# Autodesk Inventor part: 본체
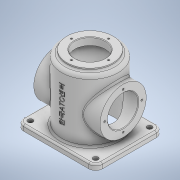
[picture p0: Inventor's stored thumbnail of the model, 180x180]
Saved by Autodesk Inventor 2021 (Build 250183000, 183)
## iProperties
Created: 2021-02
Part Number: 본체
Material: 알루미늄 6061
Document SubType Name: Modeling
Designer: 201-05
Density: 2.7 g/cm^3
Appearance: 기본값
Mass: 1235.48 g
Surface Area: 1067.61 cm^2
Volume: 457.584 cm^3
Author: 201-05
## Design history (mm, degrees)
sketch "스케치1"
  geometry: L1 (70, -60)-(-70, -60); L2 (-70, -60)-(-70, 60); L3 (-70, 60)-(70, 60); L4 (70, 60)-(70, -60); L5 (70, -60)-(-70, 60); L6 (-70, -60)-(70, 60); 1 further point
  constraints: 12 end point, 2 midpoint, 2 parallel, 1 horizontal, 1 perpendicular
  dimensions: "d0" = 140 distance of L2.end L3.end; "d1" = 120 distance of L1.end L2.end
extrude "돌출1" new body sketch "스케치1" distance "d2" = 10; taper "d3" = 0 deg
fillet "모깎기1" dims "d4" = 12
fillet "모깎기2" dims "d5" = 3
sketch "스케치2"
  geometry: A1 r 12 centre (-58, -48) between (-70, -48) and (-58, -60) reference; A2 r 12 centre (-58, 48) between (-58, 60) and (-70, 48) reference; A3 r 12 centre (58, -48) between (58, -60) and (70, -48) reference; A4 r 12 centre (58, 48) between (70, 48) and (58, 60) reference; 5 further points
  constraints: 4 coincident
hole "구멍1" sketch "스케치2" at (-58, -48), (-58, 48), (58, -48), (58, 48) diameter "d6" = 9; stored, may be unused: countersink angle "d10" = 90 deg, drill point angle "d12" = 118 deg; dims "d7" = 6, "d8" = 4, "d9" = 2, "d11" = 8
sketch "스케치3"
  geometry: C1 r 50 at (0, 0); 1 further point
  constraints: 1 centre point, 1 coincident
  dimensions: "d13" = 100 diameter of C1
extrude "돌출2" join sketch "스케치3" distance "d14" = 110; taper "d15" = 0 deg
sketch "스케치4"
  geometry: C1 r 42 at (0, 0); 1 further point
  constraints: 1 centre point, 1 coincident
  dimensions: "d16" = 84 diameter of C1
extrude "돌출3" cut sketch "스케치4" distance "d17" = 112; taper "d18" = 0 deg
sketch "스케치5"
  geometry: C1 r 27 at (0, 0); C2 r 41 at (0, 0); 1 further point
  constraints: 2 centre point, 2 coincident
  dimensions: "d19" = 54 diameter of C1; "d20" = 82 diameter of C2
extrude "돌출4" join sketch "스케치5" distance "d21" = 5; taper "d22" = 0 deg
extrude "돌출5" cut sketch "스케치5" extent not by distance; stored distance "d23" = 0; taper "d24" = 0 deg
sketch "스케치6" dims "d25" = 66
  geometry: 3 further points
  constraints: 2 vertical alignment, 1 coincident, 2 other
hole "구멍2" sketch "스케치6" at (0, 33) diameter "d26" = 3.242; stored, may be unused: countersink angle "d30" = 90 deg, drill point angle "d32" = 118 deg; dims "d27" = 8, "d28" = 4, "d29" = 2, "d31" = 10
fillet "모깎기3" dims "d36" = 3
chamfer "모따기1" distance "d37" = 1; stored, may be unused: second distance "d38" = 2, angle "d39" = 45 deg
fillet "모깎기4" dims "d40" = 6
fillet "모깎기5" dims "d41" = 3
node "작업 평면3"
sketch "스케치8"
  geometry: L1 (-25, 0)-(150, 0) reference; L2 (0, 48)-(0, -48) reference; C1 r 41 at (60, 0); 1 further point
  constraints: 1 centre point, 1 point on line
  dimensions: "d44" = 60 distance from line of L2 C1.centre; "d45" = 82 diameter of C1
extrude "돌출6" join sketch "스케치8" stored distance "d46" = 5; taper "d47" = 0 deg
sketch "스케치9" dims "d49" = 66
  geometry: C1 r 41 at (0, 0) reference; C2 r 27 at (0, 0); 3 further points
  constraints: 2 coincident, 2 vertical alignment, 1 centre point, 2 other
  dimensions: "d48" = 54 diameter of C2
hole "구멍3" sketch "스케치9" diameter "d50" = 3.242; stored, may be unused: countersink angle "d54" = 90 deg, drill point angle "d56" = 118 deg; dims "d51" = 8, "d52" = 4, "d53" = 2, "d55" = 10
extrude "돌출7" cut sketch "스케치9" extent not by distance; stored distance "d60" = 0; taper "d61" = 0 deg
chamfer "모따기2" distance "d62" = 1; stored, may be unused: second distance "d63" = 2, angle "d64" = 45 deg
chamfer "모따기3" distance "d65" = 1; stored, may be unused: second distance "d66" = 2, angle "d67" = 45 deg
fillet "모깎기6" dims "d68" = 3
fillet "모깎기7" dims "d69" = 3
node "작업 평면5"
sketch "스케치10"
  geometry: L1 (0, 140)-(0, -35) reference; L2 (-58, -10)-(58, -10) reference; 2 further points
  constraints: 1 point on line, 1 other
  dimensions: "d70" = 66 distance from line of L2 point (0, 56)
feature "엠보싱1" sketch "스케치10" dims "d0" = 140, "d1" = 120, "d71" = 0.5, "d72" = 0
node "솔리드1"
pattern_circular "원형 패턴1" dims angle "d34" = 360 deg
pattern_circular "원형 패턴2" dims angle "d58" = 360 deg
mirror "미러1"
node "작업 평면4"
feature "A9D066F2-1C7D-4E18-AEED-F7BC21143FA4" dims "d6" = 9, "d7" = 6, "d8" = 4, "d9" = 2, "d10" = 90 deg, "d11" = 8, "d12" = 118 deg
other parameters: "d43" = 59
